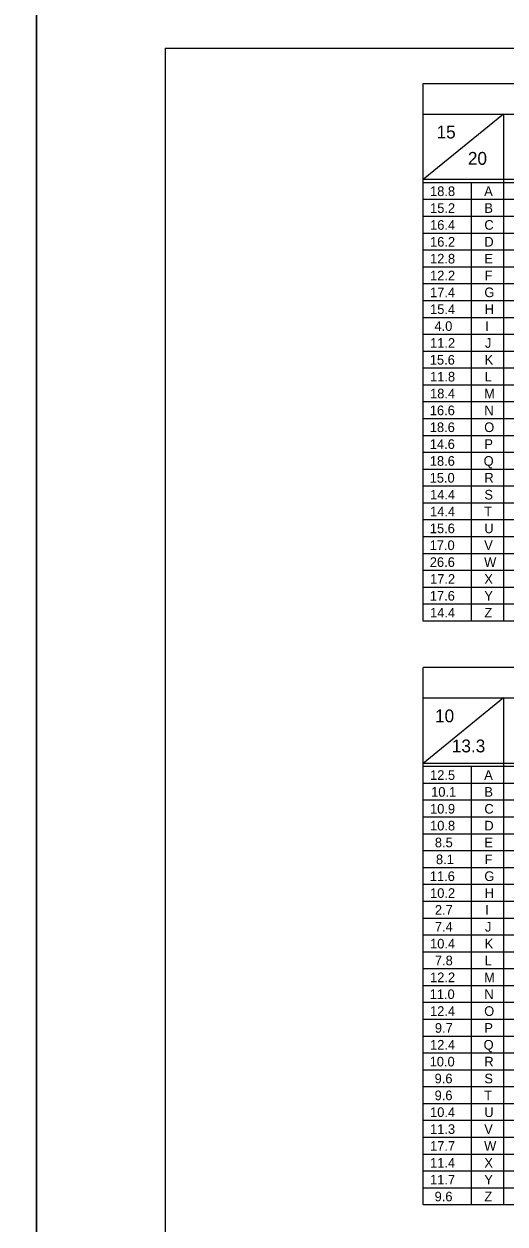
# Model space of a CAD drawing. Extents: x 638421 to 641849, y 297270 to 299646.
# Drawn here: x 639258.4 to 639408.2, y 298670.4 to 299044.1 of the extents above; entities that cross this region are included whole.
import ezdxf

# ---------------------------------------------------------------- set-up
doc = ezdxf.new("R2010")
doc.units = 0
for name, color, linetype in [('1', 7, 'Continuous'), ('2', 7, 'Continuous'), ('XCS-GRID-HVGL', 7, 'Continuous')]:
    doc.layers.add(name, color=color, linetype=linetype)

msp = doc.modelspace()

# ---------------------------------------------------------------- linework, layer by layer
at = {"layer": '1'}
for q in [(640088.31, 299036.63), (639302.31, 298472.63)]:
    msp.add_line((639302.31, 299036.63), q, dxfattribs=at)
at = {"layer": '2'}
for p, q in [((639382.73, 298858.17), (639382.73, 299025.55)), ((639382.73, 299025.55), (639661.18, 299025.55)), ((639382.73, 299016.05), (639661.18, 299016.05)), ((639407.73, 299016.05), (639382.73, 298995.67)), ((639407.73, 299016.05), (639407.73, 298858.17)), ((639661.18, 298995.67), (639382.73, 298995.67)), ((639661.18, 298994.67), (639382.73, 298994.67)), ((639390.23, 298993.55), (639390.23, 298993.55)), ((639397.73, 298994.67), (639397.73, 298858.17)), ((639402.73, 298993.55), (639402.73, 298993.55)), ((639661.18, 298989.42), (639382.73, 298989.42)), ((639661.18, 298984.17), (639382.73, 298984.17)), ((639661.18, 298978.92), (639382.73, 298978.92)), ((639661.18, 298973.67), (639382.73, 298973.67)), ((639661.18, 298968.42), (639382.73, 298968.42)), ((639661.18, 298963.17), (639382.73, 298963.17)), ((639661.18, 298957.92), (639382.73, 298957.92)), ((639661.18, 298952.67), (639382.73, 298952.67)), ((639661.18, 298947.42), (639382.73, 298947.42)), ((639661.18, 298942.17), (639382.73, 298942.17)), ((639661.18, 298936.92), (639382.73, 298936.92)), ((639661.18, 298931.67), (639382.73, 298931.67)), ((639661.18, 298926.42), (639382.73, 298926.42)), ((639661.18, 298921.17), (639382.73, 298921.17)), ((639661.18, 298915.92), (639382.73, 298915.92)), ((639661.18, 298910.67), (639382.73, 298910.67)), ((639661.18, 298905.42), (639382.73, 298905.42)), ((639661.18, 298900.17), (639382.73, 298900.17)), ((639661.18, 298894.92), (639382.73, 298894.92)), ((639661.18, 298889.67), (639382.73, 298889.67)), ((639661.18, 298884.42), (639382.73, 298884.42)), ((639661.18, 298879.17), (639382.73, 298879.17)), ((639661.18, 298873.92), (639382.73, 298873.92)), ((639661.18, 298868.67), (639382.73, 298868.67)), ((639661.18, 298863.42), (639382.73, 298863.42)), ((639661.18, 298858.17), (639382.73, 298858.17)), ((639382.73, 298676.36), (639382.73, 298843.73)), ((639661.18, 298843.73), (639382.73, 298843.73)), ((639382.73, 298834.23), (639661.18, 298834.23)), ((639407.73, 298834.23), (639382.73, 298813.86)), ((639407.73, 298834.23), (639407.73, 298676.36)), ((639661.18, 298813.86), (639382.73, 298813.86)), ((639661.18, 298812.86), (639382.73, 298812.86)), ((639397.73, 298812.86), (639397.73, 298676.36)), ((639390.23, 298811.73), (639390.23, 298811.73)), ((639402.73, 298811.73), (639402.73, 298811.73)), ((639661.18, 298807.61), (639382.73, 298807.61)), ((639661.18, 298802.36), (639382.73, 298802.36)), ((639661.18, 298797.11), (639382.73, 298797.11)), ((639661.18, 298791.86), (639382.73, 298791.86)), ((639661.18, 298786.61), (639382.73, 298786.61)), ((639661.18, 298781.36), (639382.73, 298781.36)), ((639661.18, 298776.11), (639382.73, 298776.11)), ((639661.18, 298770.86), (639382.73, 298770.86)), ((639661.18, 298765.61), (639382.73, 298765.61)), ((639661.18, 298760.36), (639382.73, 298760.36)), ((639661.18, 298755.11), (639382.73, 298755.11)), ((639661.18, 298749.86), (639382.73, 298749.86)), ((639661.18, 298744.61), (639382.73, 298744.61)), ((639661.18, 298739.36), (639382.73, 298739.36)), ((639661.18, 298734.11), (639382.73, 298734.11)), ((639661.18, 298728.86), (639382.73, 298728.86)), ((639661.18, 298723.61), (639382.73, 298723.61)), ((639661.18, 298718.36), (639382.73, 298718.36)), ((639661.18, 298713.11), (639382.73, 298713.11)), ((639661.18, 298707.86), (639382.73, 298707.86)), ((639661.18, 298702.61), (639382.73, 298702.61)), ((639661.18, 298697.36), (639382.73, 298697.36)), ((639661.18, 298692.11), (639382.73, 298692.11)), ((639661.18, 298686.86), (639382.73, 298686.86)), ((639661.18, 298681.61), (639382.73, 298681.61)), ((639661.18, 298676.36), (639382.73, 298676.36))]:
    msp.add_line(p, q, dxfattribs=at)
at = {"layer": 'XCS-GRID-HVGL'}
for points in [[(638421.31, 299051.63), (639262.31, 299051.63), (639262.31, 298457.63), (638421.31, 298457.63)], [(639262.31, 299051.63), (640103.31, 299051.63), (640103.31, 298457.63), (639262.31, 298457.63)]]:
    msp.add_lwpolyline(points, close=True, dxfattribs=at)

# ---------------------------------------------------------------- texts
at = {"layer": '2'}
for s, height, p in [('15', 4, (639386.9, 299008.47)), ('20', 4, (639396.67, 299000.28)), ('18.8', 3, (639384.88, 298990.55)), ('A', 3, (639401.75, 298990.55)), ('15.2', 3, (639384.88, 298985.3)), ('B', 3, (639401.8, 298985.3)), ('16.4', 3, (639384.88, 298980.05)), ('C', 3, (639401.8, 298980.05)), ('16.2', 3, (639384.88, 298974.8)), ('D', 3, (639401.8, 298974.8)), ('12.8', 3, (639384.88, 298969.55)), ('E', 3, (639401.81, 298969.55)), ('12.2', 3, (639384.88, 298964.3)), ('F', 3, (639401.87, 298964.3)), ('17.4', 3, (639384.88, 298959.05)), ('G', 3, (639401.8, 298959.05)), ('15.4', 3, (639384.88, 298953.8)), ('H', 3, (639401.88, 298953.8)), ('4.0', 3, (639386.25, 298948.55)), ('I', 3, (639402.05, 298948.55)), ('11.2', 3, (639384.88, 298943.3)), ('J', 3, (639401.99, 298943.3)), ('15.6', 3, (639384.8, 298938.05)), ('K', 3, (639401.88, 298938.05)), ('11.8', 3, (639384.88, 298932.8)), ('L', 3, (639401.88, 298932.8)), ('18.4', 3, (639384.88, 298927.55)), ('M', 3, (639401.73, 298927.55)), ('16.6', 3, (639384.8, 298922.3)), ('N', 3, (639401.8, 298922.3)), ('18.6', 3, (639384.8, 298917.05)), ('O', 3, (639401.75, 298917.05)), ('14.6', 3, (639384.8, 298911.8)), ('P', 3, (639401.8, 298911.8)), ('18.6', 3, (639384.8, 298906.55)), ('Q', 3, (639401.57, 298906.55)), ('15.0', 3, (639384.75, 298901.3)), ('R', 3, (639401.8, 298901.3)), ('14.4', 3, (639384.88, 298896.05)), ('S', 3, (639401.81, 298896.05)), ('14.4', 3, (639384.88, 298890.8)), ('T', 3, (639401.74, 298890.8)), ('15.6', 3, (639384.8, 298885.55)), ('U', 3, (639401.79, 298885.55)), ('17.0', 3, (639384.75, 298880.3)), ('V', 3, (639401.75, 298880.3)), ('26.6', 3, (639384.8, 298875.05)), ('W', 3, (639401.73, 298875.05)), ('17.2', 3, (639384.88, 298869.8)), ('X', 3, (639401.79, 298869.8)), ('17.6', 3, (639384.8, 298864.55)), ('Y', 3, (639401.79, 298864.55)), ('14.4', 3, (639384.88, 298859.3)), ('Z', 3, (639401.8, 298859.3)), ('10', 4, (639386.44, 298826.66)), ('13.3', 4, (639391.67, 298817.3)), ('12.5', 3, (639384.88, 298808.73)), ('A', 3, (639401.75, 298808.73)), ('10.1', 3, (639385.22, 298803.48)), ('B', 3, (639401.8, 298803.48)), ('10.9', 3, (639384.87, 298798.23)), ('C', 3, (639401.8, 298798.23)), ('10.8', 3, (639384.88, 298792.98)), ('D', 3, (639401.8, 298792.98)), ('8.5', 3, (639386.38, 298787.73)), ('E', 3, (639401.81, 298787.73)), ('8.1', 3, (639386.72, 298782.48)), ('F', 3, (639401.87, 298782.48)), ('11.6', 3, (639384.8, 298777.23)), ('G', 3, (639401.8, 298777.23)), ('10.2', 3, (639384.88, 298771.98)), ('H', 3, (639401.88, 298771.98)), ('2.7', 3, (639386.38, 298766.73)), ('I', 3, (639402.05, 298766.73)), ('7.4', 3, (639386.38, 298761.48)), ('J', 3, (639401.99, 298761.48)), ('10.4', 3, (639384.88, 298756.23)), ('K', 3, (639401.88, 298756.23)), ('7.8', 3, (639386.38, 298750.98)), ('L', 3, (639401.88, 298750.98)), ('12.2', 3, (639384.88, 298745.73)), ('M', 3, (639401.73, 298745.73)), ('11.0', 3, (639384.75, 298740.48)), ('N', 3, (639401.8, 298740.48)), ('12.4', 3, (639384.88, 298735.23)), ('O', 3, (639401.75, 298735.23)), ('9.7', 3, (639386.38, 298729.98)), ('P', 3, (639401.8, 298729.98)), ('12.4', 3, (639384.88, 298724.73)), ('Q', 3, (639401.57, 298724.73)), ('10.0', 3, (639384.75, 298719.48)), ('R', 3, (639401.8, 298719.48)), ('9.6', 3, (639386.3, 298714.23)), ('S', 3, (639401.81, 298714.23)), ('9.6', 3, (639386.3, 298708.98)), ('T', 3, (639401.74, 298708.98)), ('10.4', 3, (639384.88, 298703.73)), ('U', 3, (639401.79, 298703.73)), ('11.3', 3, (639384.88, 298698.48)), ('V', 3, (639401.75, 298698.48)), ('17.7', 3, (639384.88, 298693.23)), ('W', 3, (639401.73, 298693.23)), ('11.4', 3, (639384.88, 298687.98)), ('X', 3, (639401.79, 298687.98)), ('11.7', 3, (639384.88, 298682.73)), ('Y', 3, (639401.79, 298682.73)), ('9.6', 3, (639386.3, 298677.48)), ('Z', 3, (639401.8, 298677.48))]:
    msp.add_text(s, height=height, dxfattribs=at).set_placement(p)

doc.saveas('drawing.dxf')
